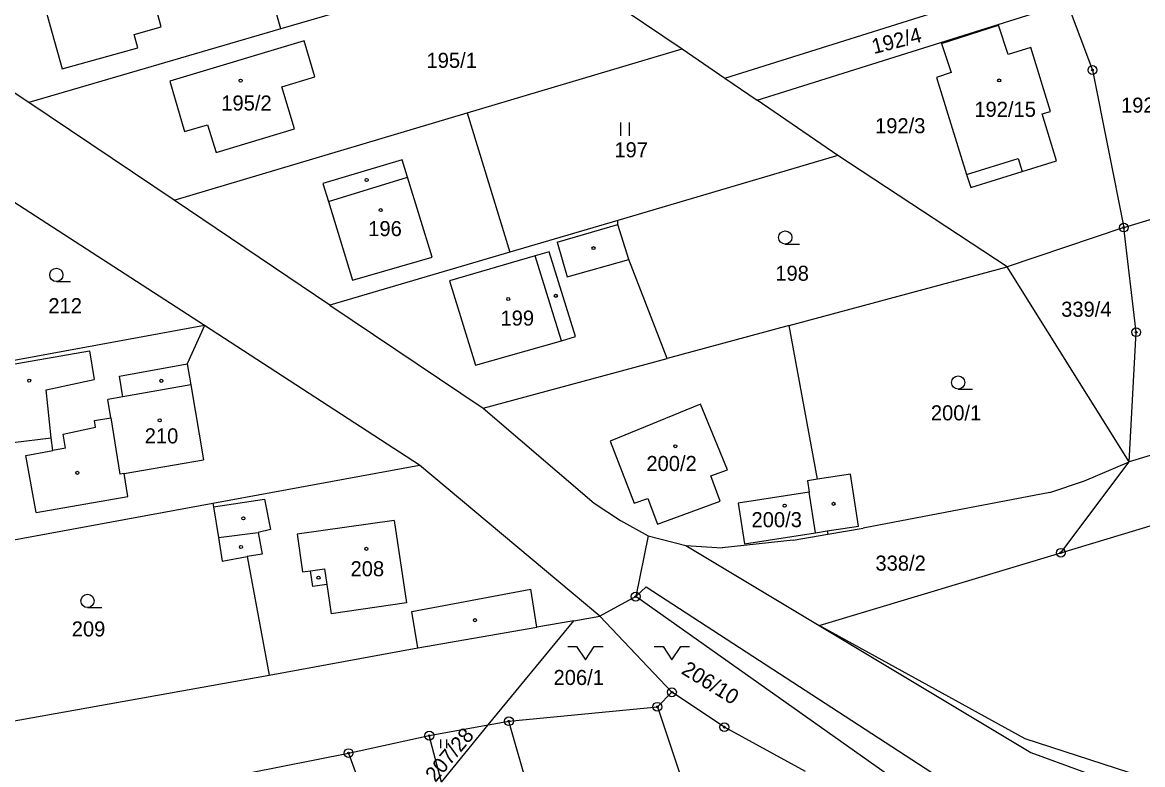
# Model space of a CAD drawing. Extents: x -762263 to -760336, y -1154405 to -1152076.
# Drawn here: x -761336.3 to -761209.8, y -1152630.1 to -1152546.3 of the extents above; entities that cross this region are included whole.
import ezdxf

# ---------------------------------------------------------------- set-up
doc = ezdxf.new("R2010")
doc.units = 0
for name, color, linetype in [('Vrstva 1', 7, 'Continuous'), ('Vrstva 18', 7, 'Continuous'), ('Vrstva 19', 7, 'Continuous'), ('Vrstva 24', 7, 'Continuous'), ('Vrstva 25', 7, 'Continuous'), ('Vrstva 4', 7, 'Continuous'), ('Vrstva 6', 7, 'Continuous')]:
    doc.layers.add(name, color=color, linetype=linetype)

msp = doc.modelspace()

# ---------------------------------------------------------------- linework, layer by layer
at = {"layer": 'Vrstva 1'}
for p, q in [((-761307.11, -1152547.04), (-761309.97, -1152537.2)), ((-761277.83, -1152538.47), (-761261.81, -1152549.3)), ((-761256.99, -1152552.61), (-761219.56, -1152540.83)), ((-761289.4, -1152541.86), (-761307.11, -1152547.04)), ((-761253.35, -1152555.1), (-761218.33, -1152544.1)), ((-761218.33, -1152544.1), (-761215.48, -1152551.69)), ((-761307.11, -1152547.04), (-761335.58, -1152555.36)), ((-761232.52, -1152548.69), (-761226.1, -1152546.63)), ((-761225.01, -1152549.92), (-761226.1, -1152546.63)), ((-761304.48, -1152548.37), (-761319.66, -1152552.96)), ((-761303.29, -1152552.47), (-761304.48, -1152548.37)), ((-761286.09, -1152556.53), (-761261.81, -1152549.3)), ((-761261.81, -1152549.3), (-761256.99, -1152552.61)), ((-761232.52, -1152548.69), (-761231.42, -1152551.97)), ((-761222.45, -1152549.14), (-761225.01, -1152549.92)), ((-761220.22, -1152556.37), (-761222.45, -1152549.14)), ((-761231.42, -1152551.97), (-761233.09, -1152552.52)), ((-761215.48, -1152551.69), (-761211.94, -1152569.47)), ((-761319.66, -1152552.96), (-761318, -1152558.61)), ((-761307, -1152553.58), (-761303.29, -1152552.47)), ((-761305.56, -1152558.32), (-761307, -1152553.58)), ((-761256.99, -1152552.61), (-761253.35, -1152555.1)), ((-761233.09, -1152552.52), (-761229.69, -1152563.47)), ((-761335.58, -1152555.36), (-761337.67, -1152553.96)), ((-761319.16, -1152566.38), (-761335.58, -1152555.36)), ((-761244.23, -1152561.35), (-761253.35, -1152555.1)), ((-761319.16, -1152566.38), (-761286.09, -1152556.53)), ((-761286.09, -1152556.53), (-761281.25, -1152572.25)), ((-761221.17, -1152556.64), (-761220.22, -1152556.37)), ((-761219.53, -1152561.93), (-761221.17, -1152556.64)), ((-761318, -1152558.61), (-761315.41, -1152557.86)), ((-761315.41, -1152557.86), (-761314.43, -1152560.99)), ((-761314.43, -1152560.99), (-761305.56, -1152558.32)), ((-761244.23, -1152561.35), (-761269.07, -1152568.66)), ((-761225.11, -1152573.9), (-761244.23, -1152561.35)), ((-761223.41, -1152563.13), (-761219.53, -1152561.93)), ((-761229.69, -1152563.47), (-761229.23, -1152564.95)), ((-761229.23, -1152564.95), (-761223.41, -1152563.13)), ((-761315.74, -1152580.53), (-761338.66, -1152565.69)), ((-761301.59, -1152578.24), (-761319.16, -1152566.38)), ((-761211.94, -1152569.47), (-761201.74, -1152566.39)), ((-761269.07, -1152568.66), (-761281.25, -1152572.25)), ((-761269.07, -1152569.12), (-761269.07, -1152568.66)), ((-761267.83, -1152573.08), (-761269.07, -1152569.12)), ((-761211.94, -1152569.47), (-761225.11, -1152573.9)), ((-761210.54, -1152581.29), (-761211.94, -1152569.47)), ((-761281.25, -1152572.25), (-761301.59, -1152578.24)), ((-761263.48, -1152584.26), (-761267.83, -1152573.08)), ((-761249.71, -1152580.54), (-761225.11, -1152573.9)), ((-761211.33, -1152595.91), (-761225.11, -1152573.9)), ((-761301.59, -1152578.24), (-761284.28, -1152589.87)), ((-761315.74, -1152580.53), (-761338.46, -1152584.69)), ((-761315.74, -1152580.53), (-761317.69, -1152584.84)), ((-761291.45, -1152596.29), (-761315.74, -1152580.53)), ((-761249.71, -1152580.54), (-761263.48, -1152584.26)), ((-761246.51, -1152597.88), (-761249.71, -1152580.54)), ((-761211.33, -1152595.91), (-761210.54, -1152581.29)), ((-761317.69, -1152584.84), (-761317.28, -1152587.22)), ((-761284.28, -1152589.87), (-761263.48, -1152584.26)), ((-761317.28, -1152587.22), (-761315.83, -1152595.69)), ((-761284.28, -1152589.87), (-761271.74, -1152600.59)), ((-761198.27, -1152591.93), (-761211.33, -1152595.91)), ((-761337.36, -1152593.73), (-761333.03, -1152593.2)), ((-761332.87, -1152594.65), (-761333.03, -1152593.2)), ((-761335.9, -1152595.2), (-761332.87, -1152594.65)), ((-761334.72, -1152601.65), (-761335.9, -1152595.2)), ((-761324.79, -1152597.23), (-761315.83, -1152595.69)), ((-761314.79, -1152600.58), (-761291.45, -1152596.29)), ((-761271.1, -1152613.33), (-761291.45, -1152596.29)), ((-761219.05, -1152606.19), (-761211.33, -1152595.91)), ((-761216.37, -1152598.08), (-761211.33, -1152595.91)), ((-761324.38, -1152599.85), (-761324.79, -1152597.23)), ((-761246.51, -1152597.88), (-761247.67, -1152598.06)), ((-761242.8, -1152597.31), (-761246.51, -1152597.88)), ((-761241.89, -1152603.18), (-761242.8, -1152597.31)), ((-761247.67, -1152598.06), (-761247.47, -1152599.36)), ((-761220.28, -1152599.38), (-761216.37, -1152598.08)), ((-761334.72, -1152601.65), (-761324.38, -1152599.85)), ((-761247.47, -1152599.36), (-761255.48, -1152600.59)), ((-761220.28, -1152599.38), (-761241.35, -1152603.41)), ((-761219.05, -1152606.19), (-761199.82, -1152600.4)), ((-761351.13, -1152607.26), (-761314.79, -1152600.58)), ((-761314.79, -1152600.58), (-761314.72, -1152601.02)), ((-761314.72, -1152601.02), (-761314.16, -1152604.45)), ((-761271.74, -1152600.59), (-761268.78, -1152602.54)), ((-761255.48, -1152600.59), (-761254.77, -1152605.17)), ((-761268.78, -1152602.54), (-761265.64, -1152604.29)), ((-761265.64, -1152604.29), (-761267.05, -1152611.14)), ((-761265.64, -1152604.29), (-761261.4, -1152605.37)), ((-761254.77, -1152605.17), (-761246.76, -1152603.93)), ((-761249.28, -1152604.76), (-761245.36, -1152604.09)), ((-761246.76, -1152603.93), (-761245.43, -1152603.73)), ((-761245.43, -1152603.73), (-761241.89, -1152603.18)), ((-761245.43, -1152603.73), (-761245.36, -1152604.09)), ((-761245.36, -1152604.09), (-761241.35, -1152603.41)), ((-761314.16, -1152604.45), (-761313.72, -1152607.14)), ((-761261.4, -1152605.37), (-761257.28, -1152605.62)), ((-761261.4, -1152605.37), (-761246.35, -1152614.4)), ((-761249.28, -1152604.76), (-761257.28, -1152605.62)), ((-761313.72, -1152607.14), (-761310.9, -1152606.63)), ((-761310.9, -1152606.63), (-761308.43, -1152620)), ((-761246.35, -1152614.4), (-761219.05, -1152606.19)), ((-761267.05, -1152611.14), (-761265.87, -1152610.03)), ((-761265.87, -1152610.03), (-761229.28, -1152633.81)), ((-761267.05, -1152611.14), (-761271.1, -1152613.33)), ((-761229.72, -1152637.48), (-761267.05, -1152611.14)), ((-761283.69, -1152625.63), (-761274.05, -1152613.86)), ((-761274.05, -1152613.86), (-761278.22, -1152614.6)), ((-761274.05, -1152613.86), (-761271.1, -1152613.33)), ((-761223.07, -1152627.2), (-761246.35, -1152614.4)), ((-761246.35, -1152614.4), (-761222.44, -1152628.75)), ((-761291.63, -1152616.93), (-761278.22, -1152614.6)), ((-761308.43, -1152620), (-761291.63, -1152616.93)), ((-761347.53, -1152626.99), (-761308.43, -1152620)), ((-761262.96, -1152621.94), (-761264.6, -1152623.58)), ((-761257.04, -1152625.88), (-761262.96, -1152621.94)), ((-761264.6, -1152623.58), (-761254.56, -1152653.41)), ((-761288.98, -1152632.1), (-761283.69, -1152625.63)), ((-761247.89, -1152630.87), (-761257.04, -1152625.88)), ((-761199.54, -1152634.84), (-761223.07, -1152627.2)), ((-761222.44, -1152628.75), (-761150.56, -1152654.88))]:
    msp.add_line(p, q, dxfattribs=at)
at = {"layer": 'Vrstva 24'}
for centre, radius in [((-761215.48, -1152551.69), 0.5), ((-761215.48, -1152551.69), 0.1), ((-761211.94, -1152569.47), 0.5), ((-761211.94, -1152569.47), 0.1), ((-761210.54, -1152581.29), 0.5), ((-761210.54, -1152581.29), 0.1), ((-761219.05, -1152606.19), 0.5), ((-761219.05, -1152606.19), 0.1), ((-761267.05, -1152611.14), 0.5), ((-761267.05, -1152611.14), 0.1), ((-761262.96, -1152621.94), 0.5), ((-761262.96, -1152621.94), 0.1), ((-761264.6, -1152623.58), 0.5), ((-761264.6, -1152623.58), 0.1), ((-761281.36, -1152625.21), 0.5), ((-761281.36, -1152625.21), 0.1), ((-761257.04, -1152625.88), 0.5), ((-761257.04, -1152625.88), 0.1), ((-761290.35, -1152626.84), 0.5), ((-761290.35, -1152626.84), 0.1), ((-761299.47, -1152628.81), 0.5), ((-761299.47, -1152628.81), 0.1)]:
    msp.add_circle(centre, radius, dxfattribs=at)
at = {"layer": 'Vrstva 25'}
for p, q in [((-761268.73, -1152559.11), (-761268.73, -1152557.61)), ((-761267.73, -1152559.11), (-761267.73, -1152557.61)), ((-761250.16, -1152571.34), (-761248.56, -1152571.34)), ((-761332.46, -1152575.57), (-761330.86, -1152575.57)), ((-761230.64, -1152587.71), (-761229.04, -1152587.71)), ((-761328.94, -1152612.38), (-761327.34, -1152612.38)), ((-761289.045, -1152628.26), (-761289.045, -1152627.255)), ((-761288.375, -1152628.26), (-761288.375, -1152627.255))]:
    msp.add_line(p, q, dxfattribs=at)
for points in [[(-761274.72, -1152616.77), (-761273.72, -1152616.77), (-761272.72, -1152618.27), (-761271.72, -1152616.77), (-761270.72, -1152616.77)], [(-761264.96, -1152616.77), (-761263.96, -1152616.77), (-761262.96, -1152618.27), (-761261.96, -1152616.77), (-761260.96, -1152616.77)]]:
    msp.add_lwpolyline(points, dxfattribs=at)
for centre, radius in [((-761311.65, -1152552.88), 0.175), ((-761226.01, -1152552.86), 0.175), ((-761297.43, -1152564.11), 0.175), ((-761295.84, -1152567.5), 0.175), ((-761250.16, -1152570.59), 0.75), ((-761271.81, -1152571.79), 0.175), ((-761332.46, -1152574.82), 0.75), ((-761281.44, -1152577.54), 0.175), ((-761276.07, -1152577.18), 0.175), ((-761335.52, -1152586.75), 0.175), ((-761230.64, -1152586.96), 0.75), ((-761320.61, -1152586.78), 0.175), ((-761320.79, -1152591.23), 0.175), ((-761262.58, -1152594.16), 0.175), ((-761330.08, -1152597.16), 0.175), ((-761244.71, -1152600.66), 0.175), ((-761250.24, -1152600.88), 0.175), ((-761311.34, -1152602.3), 0.175), ((-761311.62, -1152605.54), 0.175), ((-761297.46, -1152605.75), 0.175), ((-761302.86, -1152609.01), 0.175), ((-761328.94, -1152611.63), 0.75), ((-761285.19, -1152613.8), 0.175)]:
    msp.add_circle(centre, radius, dxfattribs=at)
at = {"layer": 'Vrstva 4'}
for p, q in [((-761320.61, -1152546.81), (-761323.19, -1152537.52)), ((-761334.8, -1152540.8), (-761331.82, -1152551.54)), ((-761323.69, -1152547.66), (-761320.61, -1152546.81)), ((-761323.27, -1152549.18), (-761323.69, -1152547.66)), ((-761331.82, -1152551.54), (-761323.27, -1152549.18)), ((-761293.41, -1152561.82), (-761302.36, -1152564.49)), ((-761292.8, -1152563.79), (-761293.41, -1152561.82)), ((-761229.69, -1152563.47), (-761223.86, -1152561.66)), ((-761223.86, -1152561.66), (-761223.41, -1152563.13)), ((-761301.74, -1152566.52), (-761292.8, -1152563.79)), ((-761290.04, -1152572.81), (-761292.8, -1152563.79)), ((-761302.36, -1152564.49), (-761301.74, -1152566.52)), ((-761301.74, -1152566.52), (-761299.02, -1152575.42)), ((-761275.92, -1152571.12), (-761269.07, -1152569.12)), ((-761275.92, -1152571.12), (-761274.77, -1152575.04)), ((-761278.41, -1152572.68), (-761288.08, -1152575.5)), ((-761276.82, -1152572.22), (-761278.41, -1152572.68)), ((-761275.44, -1152582.25), (-761278.41, -1152572.68)), ((-761273.84, -1152581.79), (-761276.82, -1152572.22)), ((-761299.02, -1152575.42), (-761290.04, -1152572.81)), ((-761274.77, -1152575.04), (-761267.83, -1152573.08)), ((-761288.08, -1152575.5), (-761285.13, -1152585.01)), ((-761285.13, -1152585.01), (-761275.44, -1152582.25)), ((-761275.44, -1152582.25), (-761273.84, -1152581.79)), ((-761338.43, -1152585.1), (-761328.72, -1152583.4)), ((-761328.72, -1152583.4), (-761328.19, -1152586.62)), ((-761325.33, -1152586.25), (-761317.69, -1152584.84)), ((-761324.97, -1152588.57), (-761325.33, -1152586.25)), ((-761333.62, -1152587.78), (-761328.19, -1152586.62)), ((-761333.03, -1152593.2), (-761333.62, -1152587.78)), ((-761317.28, -1152587.22), (-761324.97, -1152588.57)), ((-761324.97, -1152588.57), (-761326.64, -1152588.88)), ((-761326.31, -1152590.97), (-761326.64, -1152588.88)), ((-761259.73, -1152589.43), (-761269.92, -1152593.58)), ((-761256.7, -1152596.83), (-761259.73, -1152589.43)), ((-761328.16, -1152591.27), (-761326.31, -1152590.97)), ((-761328.04, -1152592.02), (-761328.16, -1152591.27)), ((-761326.31, -1152590.97), (-761325.29, -1152597.31)), ((-761331.69, -1152592.8), (-761328.04, -1152592.02)), ((-761331.41, -1152594.38), (-761331.69, -1152592.8)), ((-761269.92, -1152593.58), (-761267.23, -1152600.58)), ((-761331.41, -1152594.38), (-761332.87, -1152594.65)), ((-761324.79, -1152597.23), (-761325.29, -1152597.31)), ((-761258.55, -1152597.5), (-761256.7, -1152596.83)), ((-761257.5, -1152600.37), (-761258.55, -1152597.5)), ((-761314.72, -1152601.02), (-761308.96, -1152600.15)), ((-761308.96, -1152600.15), (-761308.28, -1152603.55)), ((-761267.23, -1152600.58), (-761265.66, -1152600.06)), ((-761265.66, -1152600.06), (-761264.6, -1152602.96)), ((-761264.6, -1152602.96), (-761257.5, -1152600.37)), ((-761246.76, -1152603.93), (-761247.47, -1152599.36)), ((-761294.32, -1152602.53), (-761305.27, -1152604.1)), ((-761294.32, -1152602.53), (-761292.93, -1152611.84)), ((-761314.16, -1152604.45), (-761309.67, -1152603.89)), ((-761308.28, -1152603.55), (-761309.67, -1152603.89)), ((-761309.67, -1152603.89), (-761309.22, -1152606.33)), ((-761305.27, -1152604.1), (-761304.66, -1152608.36)), ((-761309.22, -1152606.33), (-761310.9, -1152606.63)), ((-761303.77, -1152608.23), (-761302.18, -1152608.01)), ((-761302.18, -1152608.01), (-761301.93, -1152609.77)), ((-761304.66, -1152608.36), (-761303.77, -1152608.23)), ((-761303.51, -1152610), (-761303.77, -1152608.23)), ((-761301.93, -1152609.77), (-761303.51, -1152610)), ((-761301.93, -1152609.77), (-761301.45, -1152613.09)), ((-761292.31, -1152612.81), (-761278.89, -1152610.3)), ((-761278.22, -1152614.6), (-761278.89, -1152610.3)), ((-761292.93, -1152611.84), (-761301.45, -1152613.09)), ((-761291.63, -1152616.93), (-761292.31, -1152612.81))]:
    msp.add_line(p, q, dxfattribs=at)
at = {"layer": 'Vrstva 6'}
for p, q in [((-761271.1, -1152613.33), (-761262.96, -1152621.94)), ((-761281.36, -1152625.21), (-761264.6, -1152623.58)), ((-761290.35, -1152626.84), (-761283.69, -1152625.63)), ((-761283.69, -1152625.63), (-761281.36, -1152625.21)), ((-761272.76, -1152655.53), (-761281.36, -1152625.21)), ((-761299.47, -1152628.81), (-761290.35, -1152626.84)), ((-761288.98, -1152632.1), (-761290.35, -1152626.84)), ((-761314.49, -1152631.78), (-761299.47, -1152628.81)), ((-761299.47, -1152628.81), (-761287.06, -1152663.15))]:
    msp.add_line(p, q, dxfattribs=at)

# ---------------------------------------------------------------- texts
at = {"layer": 'Vrstva 18'}
for s, rotation, p in [('192/4', 14.38124, (-761240.15, -1152549.892)), ('206/10', 328.36211, (-761262.012, -1152619.763)), ('207/28', 50.1911, (-761289.658, -1152632.195))]:
    msp.add_text(s, height=1.7, rotation=rotation, dxfattribs=at).set_placement(p)
for s, p in [('195/1', (-761290.667, -1152551.44)), ('192/13', (-761212.257, -1152556.5)), ('192/3', (-761240.027, -1152558.82)), ('197', (-761269.457, -1152561.54)), ('198', (-761251.287, -1152575.48)), ('212', (-761333.363, -1152579.14)), ('339/4', (-761219.013, -1152579.54)), ('200/1', (-761233.723, -1152591.24)), ('338/2', (-761239.983, -1152608.21)), ('209', (-761330.723, -1152615.64)), ('206/1', (-761276.326, -1152621.12))]:
    msp.add_text(s, height=1.7, dxfattribs=at).set_placement(p)
at = {"layer": 'Vrstva 19'}
for s, p in [('195/2', (-761313.837, -1152556.26)), ('192/15', (-761228.817, -1152556.97)), ('196', (-761297.247, -1152570.44)), ('199', (-761282.317, -1152580.54)), ('210', (-761322.483, -1152593.84)), ('200/2', (-761265.843, -1152596.96)), ('200/3', (-761253.973, -1152603.3)), ('208', (-761299.243, -1152608.84))]:
    msp.add_text(s, height=1.7, dxfattribs=at).set_placement(p)

doc.saveas('drawing.dxf')
